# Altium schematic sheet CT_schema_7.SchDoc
size 278 x 170 mm
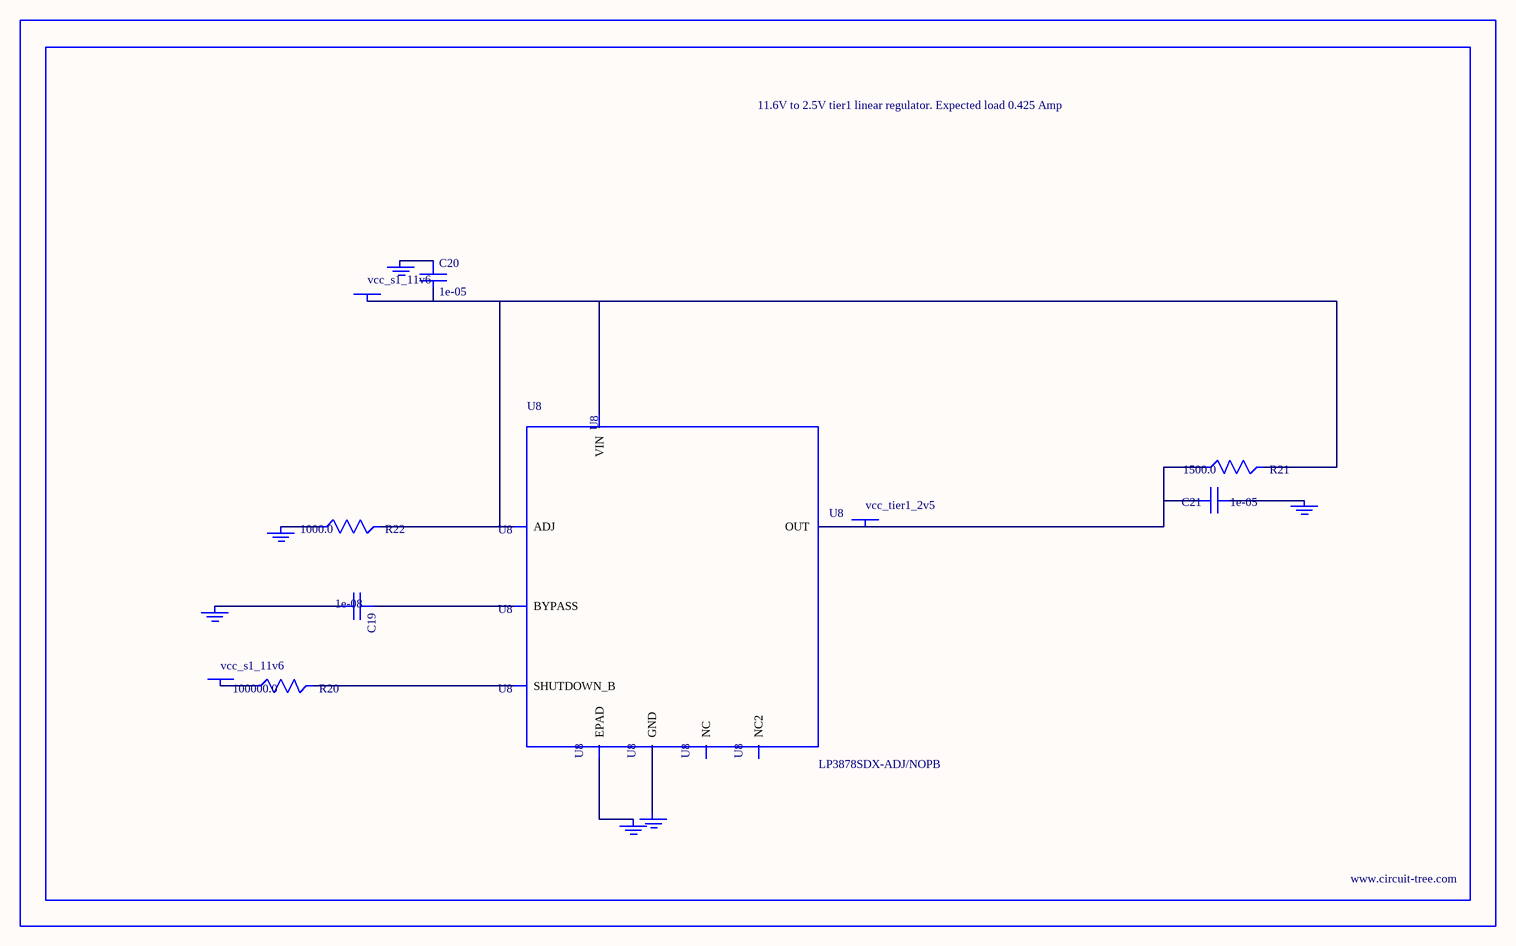
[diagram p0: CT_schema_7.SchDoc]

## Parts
BORDER6  (no value)
C19  1e-08  [C0402]
C20  1e-05  [C1210]
C21  1e-05  [C1210]
GND_INSTANCE_6_0  (no value)
GND_INSTANCE_6_1  (no value)
GND_INSTANCE_6_2  (no value)
GND_INSTANCE_6_3  (no value)
GND_INSTANCE_6_4  (no value)
GND_INSTANCE_6_5  (no value)
POWER_INSTANCE_6_0  vcc_s1_11v6
POWER_INSTANCE_6_1  vcc_s1_11v6
POWER_INSTANCE_6_2  vcc_tier1_2v5
R20  100000.0  [R0603]
R21  1500.0  [R0603]
R22  1000.0  [R0603]
U8  LP3878SDX-ADJ/NOPB  [WSON-8]

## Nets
NetC19_1: C19.1 U8.1(BYPASS)
NetC19_2: C19.2 GND_INSTANCE_6_0.0(GND)
NetC20_1: C20.1 GND_INSTANCE_6_1.0(GND)
NetC20_2: C20.2 POWER_INSTANCE_6_0.0(PWR) R21.2 R22.2 U8.4(VIN) U8.6(ADJ)
NetC21_1: C21.1 GND_INSTANCE_6_2.0(GND)
NetC21_2: C21.2 POWER_INSTANCE_6_2.0(PWR) R21.1 U8.5(OUT)
NetGND_INSTANCE_6_3_0: GND_INSTANCE_6_3.0(GND) R22.1
NetGND_INSTANCE_6_4_0: GND_INSTANCE_6_4.0(GND) U8.PAD(EPAD)
NetGND_INSTANCE_6_5_0: GND_INSTANCE_6_5.0(GND) U8.3(GND)
NetPOWER_INSTANCE_6_1_0: POWER_INSTANCE_6_1.0(PWR) R20.1
NetR20_2: R20.2 U8.8(SHUTDOWN_B)

Not connected (* = marked no-connect by the designer): U8 2(NC) 7(NC2)

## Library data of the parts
BORDER6 = BORDER_PAGE6
C19 = C0402C103K3RAC
C20 = C1210C106K5PACTU
C21 = GRM32DR61E106MA12L
GND_INSTANCE_6_0-GND_INSTANCE_6_5 = GND
POWER_INSTANCE_6_0-POWER_INSTANCE_6_2 = PWR
R20 = RC0603JR-07100KL
R21 = RC0603JR-071K5L
R22 = RC0603JR-071KL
